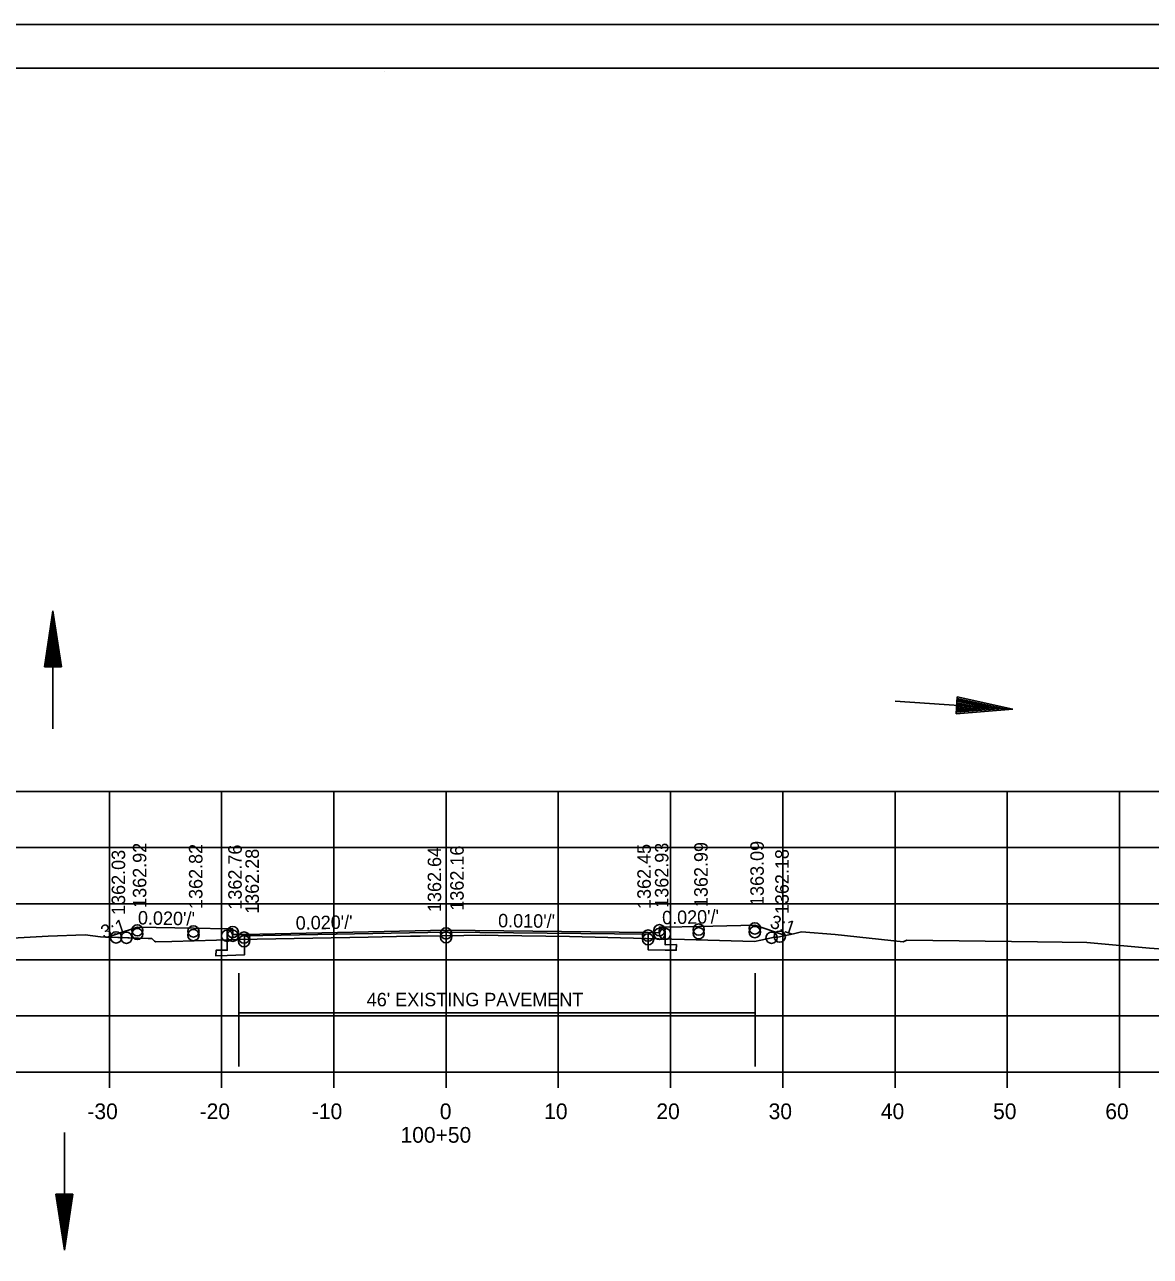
# Model space of a CAD drawing. Extents: x 1374311 to 1383814, y 384102 to 406278.
# Drawn here: x 1382683.3 to 1382783.6, y 384796.1 to 384905.9 of the extents above; entities that cross this region are included whole.
import ezdxf

# ---------------------------------------------------------------- set-up
doc = ezdxf.new("R2010")
doc.units = 0
for name, color, linetype in [('R_Axis', 7, 'Continuous'), ('R_Axis Annot', 7, 'Continuous'), ('R_Border', 7, 'Continuous'), ('R_Draft', 7, 'Continuous'), ('R_Exist Surface', 7, 'Continuous'), ('R_Fin Surface', 7, 'Continuous'), ('R_Grid', 7, 'Continuous'), ('R_No Plot', 7, 'Continuous'), ('R_Water', 7, 'Continuous'), ('R_Xsect Elev', 7, 'Continuous'), ('R_Xsect Slope', 7, 'Continuous')]:
    doc.layers.add(name, color=color, linetype=linetype)

msp = doc.modelspace()

# ---------------------------------------------------------------- linework, layer by layer
at = {"layer": 'R_Axis'}
for p, q in [((1382580.86, 384812.54), (1382860.86, 384812.54)), ((1382690.86, 384811.14), (1382690.86, 384812.54)), ((1382700.86, 384811.14), (1382700.86, 384812.54)), ((1382710.86, 384811.14), (1382710.86, 384812.54)), ((1382720.86, 384811.14), (1382720.86, 384812.54)), ((1382730.86, 384811.14), (1382730.86, 384812.54)), ((1382740.86, 384811.14), (1382740.86, 384812.54)), ((1382750.86, 384811.14), (1382750.86, 384812.54)), ((1382760.86, 384811.14), (1382760.86, 384812.54)), ((1382770.86, 384811.14), (1382770.86, 384812.54)), ((1382780.86, 384811.14), (1382780.86, 384812.54))]:
    msp.add_line(p, q, dxfattribs=at)
at = {"layer": 'R_Border'}
for p, q in [((1382562.86, 384902), (1382879.04, 384902)), ((1382715.38, 384901.74), (1382715.38, 384901.74)), ((1382715.38, 384901.74), (1382715.38, 384901.74))]:
    msp.add_line(p, q, dxfattribs=at)
at = {"layer": 'R_Draft'}
for p, q in [((1382685.08, 384848.64), (1382685.83, 384853.64)), ((1382686.58, 384848.64), (1382685.83, 384853.64)), ((1382685.21, 384848.64), (1382685.83, 384852.81)), ((1382686.46, 384848.64), (1382685.83, 384852.81)), ((1382685.33, 384848.64), (1382685.83, 384851.95)), ((1382686.33, 384848.64), (1382685.83, 384851.95)), ((1382685.46, 384848.64), (1382685.83, 384851.12)), ((1382685.59, 384848.64), (1382685.83, 384850.27)), ((1382686.2, 384848.64), (1382685.83, 384851.12)), ((1382686.08, 384848.64), (1382685.83, 384850.27)), ((1382685.71, 384848.64), (1382685.83, 384849.43)), ((1382685.95, 384848.64), (1382685.83, 384849.43)), ((1382685.08, 384848.64), (1382686.58, 384848.64)), ((1382766.41, 384845.97), (1382766.31, 384844.47)), ((1382766.4, 384845.84), (1382770.51, 384844.93)), ((1382766.41, 384845.97), (1382771.35, 384844.88)), ((1382766.31, 384844.6), (1382770.51, 384844.93)), ((1382766.31, 384844.47), (1382771.35, 384844.88)), ((1382766.32, 384844.72), (1382769.65, 384844.99)), ((1382766.33, 384844.85), (1382768.82, 384845.05)), ((1382766.34, 384844.98), (1382767.98, 384845.11)), ((1382766.35, 384845.1), (1382767.15, 384845.17)), ((1382766.37, 384845.46), (1382767.98, 384845.11)), ((1382766.37, 384845.34), (1382767.15, 384845.17)), ((1382766.38, 384845.59), (1382768.82, 384845.05)), ((1382766.39, 384845.72), (1382769.65, 384844.99)), ((1382686.1, 384801.65), (1382686.85, 384796.65)), ((1382687.6, 384801.65), (1382686.1, 384801.65)), ((1382686.22, 384801.65), (1382686.85, 384797.48)), ((1382686.35, 384801.65), (1382686.85, 384798.34)), ((1382686.48, 384801.65), (1382686.85, 384799.17)), ((1382686.6, 384801.65), (1382686.85, 384800.02)), ((1382686.73, 384801.65), (1382686.85, 384800.86)), ((1382687.6, 384801.65), (1382686.85, 384796.65)), ((1382687.09, 384801.65), (1382686.85, 384800.02)), ((1382687.35, 384801.65), (1382686.85, 384798.34)), ((1382687.47, 384801.65), (1382686.85, 384797.48)), ((1382687.22, 384801.65), (1382686.85, 384799.17)), ((1382686.97, 384801.65), (1382686.85, 384800.86))]:
    msp.add_line(p, q, dxfattribs=at)
at = {"layer": 'R_Exist Surface'}
msp.add_lwpolyline([(1382676.81, 384824.16), (1382685.41, 384824.64), (1382688.69, 384824.76), (1382690.08, 384824.58), (1382694.32, 384824.45), (1382694.42, 384824.45), (1382694.63, 384824.45), (1382694.88, 384824.2), (1382695, 384824.14), (1382696.43, 384824.18), (1382702.4, 384824.36), (1382713.92, 384824.57), (1382717.69, 384824.65), (1382718.56, 384824.66), (1382724.39, 384824.74), (1382725.49, 384824.72), (1382731.86, 384824.63), (1382742.1, 384824.35), (1382748.33, 384824.18), (1382748.9, 384824.3), (1382750.11, 384824.57), (1382750.26, 384824.57), (1382750.41, 384824.57), (1382751.82, 384824.86), (1382752.53, 384825.03), (1382755.52, 384824.79), (1382761.59, 384824.13), (1382761.91, 384824.3), (1382773.56, 384824.13), (1382777.96, 384824.09), (1382783.53, 384823.58), (1382785.18, 384823.47)], dxfattribs=at)
at = {"layer": 'R_Fin Surface'}
for points in [[(1382690.69, 384824.56), (1382693.35, 384825.45), (1382698.35, 384825.35), (1382701.35, 384825.29), (1382701.85, 384825.29), (1382701.86, 384824.79), (1382702.86, 384824.81), (1382720.86, 384825.17), (1382738.86, 384824.98), (1382739.86, 384824.96), (1382739.87, 384825.46), (1382740.37, 384825.46), (1382743.37, 384825.52), (1382748.37, 384825.62), (1382751.11, 384824.71)], [(1382740.37, 384825.13), (1382740.38, 384823.89), (1382741.38, 384823.9), (1382741.37, 384823.4), (1382740.37, 384823.41), (1382738.87, 384823.43), (1382738.87, 384824.83), (1382720.86, 384825), (1382702.89, 384824.67), (1382702.89, 384822.98), (1382701.35, 384822.92), (1382700.35, 384822.89), (1382700.36, 384823.39), (1382701.36, 384823.4), (1382701.35, 384825.29)]]:
    msp.add_lwpolyline(points, dxfattribs=at)
at = {"layer": 'R_Grid'}
for p, q in [((1382580.86, 384837.54), (1382860.86, 384837.54)), ((1382690.86, 384812.54), (1382690.86, 384837.54)), ((1382700.86, 384812.54), (1382700.86, 384837.54)), ((1382710.86, 384812.54), (1382710.86, 384837.54)), ((1382720.86, 384812.54), (1382720.86, 384837.54)), ((1382730.86, 384812.54), (1382730.86, 384837.54)), ((1382740.86, 384812.54), (1382740.86, 384837.54)), ((1382750.86, 384812.54), (1382750.86, 384837.54)), ((1382760.86, 384812.54), (1382760.86, 384837.54)), ((1382770.86, 384812.54), (1382770.86, 384837.54)), ((1382780.86, 384812.54), (1382780.86, 384837.54)), ((1382580.86, 384832.54), (1382860.86, 384832.54)), ((1382580.86, 384827.54), (1382860.86, 384827.54)), ((1382580.86, 384822.54), (1382860.86, 384822.54)), ((1382580.86, 384817.54), (1382860.86, 384817.54)), ((1382580.86, 384812.54), (1382860.86, 384812.54))]:
    msp.add_line(p, q, dxfattribs=at)
at = {"layer": 'R_No Plot'}
msp.add_line((1382550.46, 384905.89), (1382883.79, 384905.89), dxfattribs=at)
for points in [[(1382550.45, 384905.89), (1382883.79, 384905.89), (1382883.79, 384692.55), (1382550.45, 384692.55)], [(1382796.78, 384902), (1382796.78, 384892.12), (1382832.51, 384892.12), (1382832.51, 384889.2), (1382855.71, 384889.2), (1382855.71, 384865.98), (1382879.04, 384865.98), (1382879.04, 384696.54), (1382562.86, 384696.54), (1382562.86, 384902)], [(1382690.69, 384824.56), (1382694.32, 384824.45), (1382694.42, 384824.45), (1382694.63, 384824.45), (1382694.88, 384824.2), (1382695, 384824.14), (1382696.43, 384824.18), (1382702.4, 384824.36), (1382713.92, 384824.57), (1382717.69, 384824.65), (1382718.56, 384824.66), (1382724.39, 384824.74), (1382725.49, 384824.72), (1382731.86, 384824.63), (1382742.1, 384824.35), (1382748.33, 384824.18), (1382748.9, 384824.3), (1382750.11, 384824.57), (1382750.26, 384824.57), (1382750.41, 384824.57), (1382751.11, 384824.71), (1382748.37, 384825.62), (1382743.37, 384825.52), (1382740.37, 384825.46), (1382739.87, 384825.46), (1382739.86, 384824.96), (1382738.86, 384824.98), (1382720.86, 384825.17), (1382702.86, 384824.81), (1382701.86, 384824.79), (1382701.85, 384825.29), (1382701.35, 384825.29), (1382701.35, 384825.29), (1382698.35, 384825.35), (1382693.35, 384825.45)]]:
    msp.add_lwpolyline(points, close=True, dxfattribs=at)
for centre in [(1382691.46, 384824.54), (1382691.46, 384824.54), (1382692.38, 384824.51), (1382692.38, 384824.51), (1382693.35, 384825.17), (1382693.35, 384824.84), (1382698.35, 384825.07), (1382698.35, 384824.74), (1382701.35, 384824.68), (1382701.85, 384825.01), (1382701.85, 384824.68), (1382702.86, 384824.53), (1382720.86, 384824.89), (1382720.86, 384824.56), (1382738.86, 384824.7), (1382739.87, 384825.18), (1382739.87, 384824.85), (1382740.37, 384824.85), (1382743.37, 384825.24), (1382743.37, 384824.91), (1382748.37, 384825.34), (1382748.37, 384825.01), (1382749.86, 384824.51), (1382750.59, 384824.61), (1382702.86, 384824.2), (1382738.86, 384824.37)]:
    msp.add_circle(centre, 0.5, dxfattribs=at)
at = {"layer": 'R_Water'}
for p, q in [((1382685.83, 384843.14), (1382685.83, 384853.64)), ((1382760.87, 384845.6), (1382771.35, 384844.88)), ((1382702.4, 384813.04), (1382702.4, 384821.36)), ((1382748.4, 384813.04), (1382748.4, 384821.36)), ((1382702.4, 384817.83), (1382748.4, 384817.83)), ((1382686.85, 384807.15), (1382686.85, 384796.65))]:
    msp.add_line(p, q, dxfattribs=at)

# ---------------------------------------------------------------- texts
at = {"layer": 'R_Axis Annot'}
for s, p in [('-30', (1382688.9, 384808.34)), ('-20', (1382698.9, 384808.34)), ('-10', (1382708.9, 384808.34)), ('0', (1382720.3, 384808.34)), ('10', (1382729.6, 384808.34)), ('20', (1382739.6, 384808.34)), ('30', (1382749.6, 384808.34)), ('40', (1382759.6, 384808.34)), ('50', (1382769.6, 384808.34)), ('60', (1382779.6, 384808.34)), ('100+50', (1382716.8, 384806.24))]:
    msp.add_text(s, height=1.4, dxfattribs=at).set_placement(p)
at = {"layer": 'R_Water'}
msp.add_text("46' EXISTING PAVEMENT", height=1.2, dxfattribs=at).set_placement((1382713.79, 384818.4))
at = {"layer": 'R_Xsect Elev'}
for s, p in [('1362.92', (1382694.15, 384827.17)), ('1362.82', (1382699.15, 384827.07)), ('1362.76', (1382702.65, 384827.01)), ('1362.16', (1382722.43, 384826.92)), ('1362.45', (1382739.1, 384827.07)), ('1362.93', (1382740.67, 384827.18)), ('1362.99', (1382744.17, 384827.24)), ('1363.09', (1382749.17, 384827.34)), ('1362.03', (1382692.26, 384826.54)), ('1362.28', (1382704.18, 384826.64)), ('1362.64', (1382720.42, 384826.8)), ('1362.18', (1382751.39, 384826.61))]:
    msp.add_text(s, height=1.2, rotation=90, dxfattribs=at).set_placement(p)
at = {"layer": 'R_Xsect Slope'}
for s, rotation, p in [('3:1', 18.4349, (1382690.33, 384824.39)), ("0.020'/'", 358.8542, (1382693.39, 384825.7)), ("0.020'/'", 1.1458, (1382707.47, 384825.22)), ("0.010'/'", 359.4025, (1382725.49, 384825.44)), ("0.020'/'", 1.1458, (1382740.12, 384825.7)), ('3:1', 341.5651, (1382749.64, 384825.45))]:
    msp.add_text(s, height=1.2, rotation=rotation, dxfattribs=at).set_placement(p)

doc.saveas('drawing.dxf')
